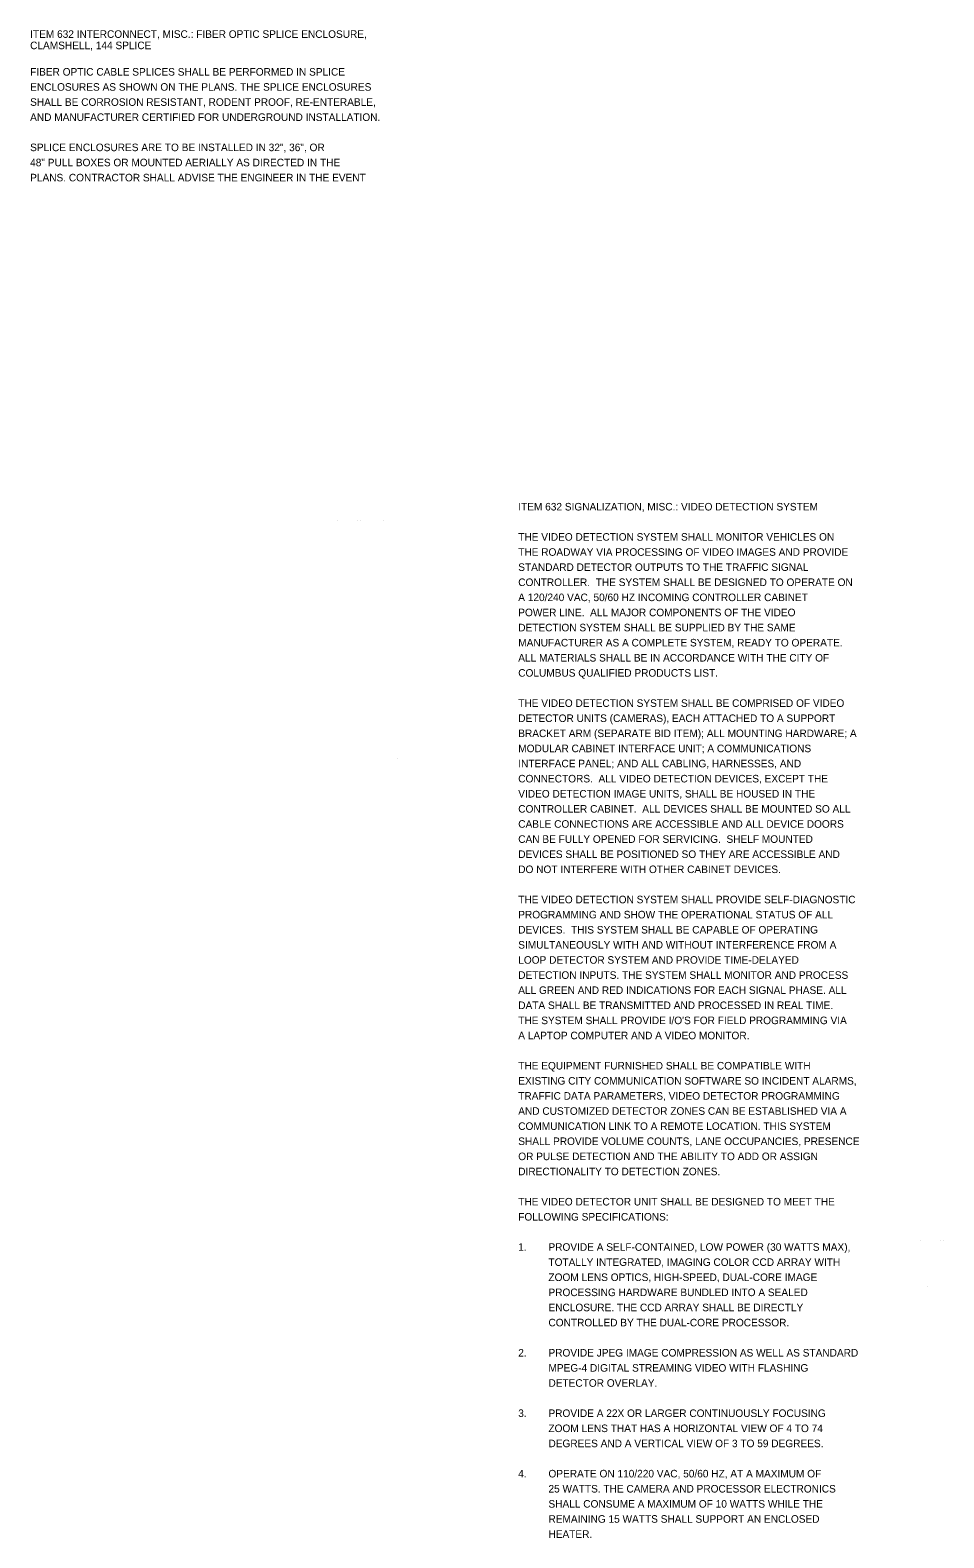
# Model space of a CAD drawing. Extents: x -39 to 75, y -25 to 14.
# Drawn here: x 36.38 to 53.32, y -23.61 to 4.33 of the extents above; entities that cross this region are included whole.
import ezdxf

# ---------------------------------------------------------------- set-up
doc = ezdxf.new("R2010")
doc.units = 0
for name, color, linetype in [('Default', 7, 'Continuous'), ('SH_Data', 7, 'Continuous'), ('SH_Text', 7, 'Continuous')]:
    doc.layers.add(name, color=color, linetype=linetype)

# ---------------------------------------------------------------- blocks, each defined once
blk = doc.blocks.new('POINT_DISPLAY')
at = {"layer": 'Default'}
blk.add_line((0, 0), (0, 0), dxfattribs=at)

msp = doc.modelspace()

# ---------------------------------------------------------------- block references
at = {"layer": 'Default', "xscale": 3.9370000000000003, "yscale": 3.9370000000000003}
for p in [(42.08, -4.749), (42.08, -4.749), (42.446, -4.749), (42.507, -4.749), (42.935, -4.749), (43.185, -9.166), (52.888, -18.102), (52.888, -18.102), (53.254, -18.102), (53.316, -18.102), (53.01, -18.957)]:
    msp.add_blockref('POINT_DISPLAY', p, dxfattribs=at)

# ---------------------------------------------------------------- texts
at = {"layer": 'SH_Data'}
for s, p in [('ITEM 632 INTERCONNECT, MISC.: FIBER OPTIC SPLICE ENCLOSURE, ', (36.38, 4.19)), ('CLAMSHELL, 144 SPLICE', (36.38, 3.98))]:
    msp.add_text(s, height=0.14, dxfattribs=at).set_placement(p)
msp.add_text('ITEM 632 SIGNALIZATION, MISC.: VIDEO DETECTION SYSTEM', height=0.14, rotation=360, dxfattribs=at).set_placement((45.427, -4.569))
at = {"layer": 'SH_Text'}
for s, p in [('FIBER OPTIC CABLE SPLICES SHALL BE PERFORMED IN SPLICE ', (36.38, 3.49)), ('ENCLOSURES AS SHOWN ON THE PLANS. THE SPLICE ENCLOSURES ', (36.38, 3.21)), ('SHALL BE CORROSION RESISTANT, RODENT PROOF, RE-ENTERABLE, ', (36.38, 2.93)), ('AND MANUFACTURER CERTIFIED FOR UNDERGROUND INSTALLATION.', (36.38, 2.65)), ('SPLICE ENCLOSURES ARE TO BE INSTALLED IN 32", 36", OR ', (36.38, 2.09)), ('48" PULL BOXES OR MOUNTED AERIALLY AS DIRECTED IN THE ', (36.38, 1.81)), ('PLANS. CONTRACTOR SHALL ADVISE THE ENGINEER IN THE EVENT ', (36.38, 1.53))]:
    msp.add_text(s, height=0.14, dxfattribs=at).set_placement(p)
for s, p in [('THE VIDEO DETECTION SYSTEM SHALL MONITOR VEHICLES ON ', (45.427, -5.129)), ('THE ROADWAY VIA PROCESSING OF VIDEO IMAGES AND PROVIDE ', (45.427, -5.409)), ('STANDARD DETECTOR OUTPUTS TO THE TRAFFIC SIGNAL ', (45.427, -5.689)), ('CONTROLLER.  THE SYSTEM SHALL BE DESIGNED TO OPERATE ON ', (45.427, -5.969)), ('A 120/240 VAC, 50/60 HZ INCOMING CONTROLLER CABINET ', (45.427, -6.249)), ('POWER LINE.  ALL MAJOR COMPONENTS OF THE VIDEO ', (45.427, -6.529)), ('DETECTION SYSTEM SHALL BE SUPPLIED BY THE SAME ', (45.427, -6.809)), ('MANUFACTURER AS A COMPLETE SYSTEM, READY TO OPERATE. ', (45.427, -7.089)), ('ALL MATERIALS SHALL BE IN ACCORDANCE WITH THE CITY OF ', (45.427, -7.369)), ('COLUMBUS QUALIFIED PRODUCTS LIST.', (45.427, -7.649)), ('THE VIDEO DETECTION SYSTEM SHALL BE COMPRISED OF VIDEO ', (45.427, -8.209)), ('DETECTOR UNITS (CAMERAS), EACH ATTACHED TO A SUPPORT ', (45.427, -8.489)), ('BRACKET ARM (SEPARATE BID ITEM); ALL MOUNTING HARDWARE; A ', (45.427, -8.769)), ('MODULAR CABINET INTERFACE UNIT; A COMMUNICATIONS ', (45.427, -9.049)), ('INTERFACE PANEL; AND ALL CABLING, HARNESSES, AND ', (45.427, -9.329)), ('CONNECTORS.  ALL VIDEO DETECTION DEVICES, EXCEPT THE ', (45.427, -9.609)), ('VIDEO DETECTION IMAGE UNITS, SHALL BE HOUSED IN THE ', (45.427, -9.889)), ('CONTROLLER CABINET.  ALL DEVICES SHALL BE MOUNTED SO ALL ', (45.427, -10.169)), ('CABLE CONNECTIONS ARE ACCESSIBLE AND ALL DEVICE DOORS ', (45.427, -10.449)), ('CAN BE FULLY OPENED FOR SERVICING.  SHELF MOUNTED ', (45.427, -10.729)), ('DEVICES SHALL BE POSITIONED SO THEY ARE ACCESSIBLE AND ', (45.427, -11.009)), ('DO NOT INTERFERE WITH OTHER CABINET DEVICES.', (45.427, -11.289)), ('THE VIDEO DETECTION SYSTEM SHALL PROVIDE SELF-DIAGNOSTIC ', (45.427, -11.849)), ('PROGRAMMING AND SHOW THE OPERATIONAL STATUS OF ALL ', (45.427, -12.129)), ('DEVICES.  THIS SYSTEM SHALL BE CAPABLE OF OPERATING ', (45.427, -12.409)), ('SIMULTANEOUSLY WITH AND WITHOUT INTERFERENCE FROM A ', (45.427, -12.689)), ('LOOP DETECTOR SYSTEM AND PROVIDE TIME-DELAYED ', (45.427, -12.969)), ('DETECTION INPUTS. THE SYSTEM SHALL MONITOR AND PROCESS ', (45.427, -13.249)), ('ALL GREEN AND RED INDICATIONS FOR EACH SIGNAL PHASE. ALL ', (45.427, -13.529)), ('DATA SHALL BE TRANSMITTED AND PROCESSED IN REAL TIME. ', (45.427, -13.809)), ("THE SYSTEM SHALL PROVIDE I/O'S FOR FIELD PROGRAMMING VIA ", (45.427, -14.089)), ('A LAPTOP COMPUTER AND A VIDEO MONITOR.', (45.427, -14.369)), ('THE EQUIPMENT FURNISHED SHALL BE COMPATIBLE WITH ', (45.427, -14.929)), ('EXISTING CITY COMMUNICATION SOFTWARE SO INCIDENT ALARMS, ', (45.427, -15.209)), ('TRAFFIC DATA PARAMETERS, VIDEO DETECTOR PROGRAMMING ', (45.427, -15.489)), ('AND CUSTOMIZED DETECTOR ZONES CAN BE ESTABLISHED VIA A ', (45.427, -15.769)), ('COMMUNICATION LINK TO A REMOTE LOCATION. THIS SYSTEM ', (45.427, -16.049)), ('SHALL PROVIDE VOLUME COUNTS, LANE OCCUPANCIES, PRESENCE ', (45.427, -16.329)), ('OR PULSE DETECTION AND THE ABILITY TO ADD OR ASSIGN ', (45.427, -16.609)), ('DIRECTIONALITY TO DETECTION ZONES. ', (45.427, -16.889)), ('THE VIDEO DETECTOR UNIT SHALL BE DESIGNED TO MEET THE ', (45.427, -17.449)), ('FOLLOWING SPECIFICATIONS:', (45.427, -17.729)), ('1.', (45.427, -18.289)), ('PROVIDE A SELF-CONTAINED, LOW POWER (30 WATTS MAX), ', (45.987, -18.289)), ('TOTALLY INTEGRATED, IMAGING COLOR CCD ARRAY WITH ', (45.987, -18.569)), ('ZOOM LENS OPTICS, HIGH-SPEED, DUAL-CORE IMAGE ', (45.987, -18.849)), ('PROCESSING HARDWARE BUNDLED INTO A SEALED ', (45.987, -19.129)), ('ENCLOSURE. THE CCD ARRAY SHALL BE DIRECTLY ', (45.987, -19.409)), ('CONTROLLED BY THE DUAL-CORE PROCESSOR.', (45.987, -19.689)), ('2.', (45.427, -20.249)), ('PROVIDE JPEG IMAGE COMPRESSION AS WELL AS STANDARD ', (45.987, -20.249)), ('MPEG-4 DIGITAL STREAMING VIDEO WITH FLASHING ', (45.987, -20.529)), ('DETECTOR OVERLAY.', (45.987, -20.809)), ('3.', (45.427, -21.369)), ('PROVIDE A 22X OR LARGER CONTINUOUSLY FOCUSING ', (45.987, -21.369)), ('ZOOM LENS THAT HAS A HORIZONTAL VIEW OF 4 TO 74 ', (45.987, -21.649)), ('DEGREES AND A VERTICAL VIEW OF 3 TO 59 DEGREES.', (45.987, -21.929)), ('4.', (45.427, -22.489)), ('OPERATE ON 110/220 VAC, 50/60 HZ, AT A MAXIMUM OF ', (45.987, -22.489)), ('25 WATTS. THE CAMERA AND PROCESSOR ELECTRONICS ', (45.987, -22.769)), ('SHALL CONSUME A MAXIMUM OF 10 WATTS WHILE THE ', (45.987, -23.049)), ('REMAINING 15 WATTS SHALL SUPPORT AN ENCLOSED ', (45.987, -23.329)), ('HEATER.', (45.987, -23.609))]:
    msp.add_text(s, height=0.14, rotation=360, dxfattribs=at).set_placement(p)

doc.saveas('drawing.dxf')
